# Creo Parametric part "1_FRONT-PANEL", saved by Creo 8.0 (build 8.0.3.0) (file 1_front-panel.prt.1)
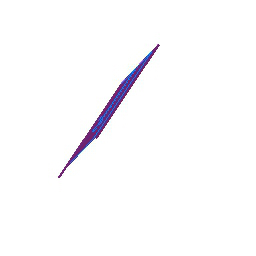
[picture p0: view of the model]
Units: millimeter Newton Second (mmNs); MM, TONNE, SECS

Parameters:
  SMT_DFLT_BEND_REL_LENGTH_TYPE = "Through All"

Other parameters: SMT_THICKNESS, SMT_PART_BEND_ALLOWANCE_FACTOR, SMT_DFLT_BEND_RADIUS, SMT_DFLT_BEND_ANGLE, SMT_DFLT_CRNR_REL_WIDTH, SMT_DFLT_CRNR_REL_DEPTH, SMT_DFLT_BEND_REL_WIDTH, SMT_DFLT_BEND_REL_DEPTH, SMT_DFLT_BEND_REL_LENGTH, SMT_DFLT_BEND_REL_ANGLE, SMT_GAP, SMT_DFLT_EDGE_TREA_WIDTH, SMT_DFLT_MITER_CUT_WIDTH, SMT_DFLT_MITER_CUT_OFFSET

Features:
  1. datum plane "DTM1"
  2. datum plane "DTM2"
  3. datum plane "DTM3"
  4. coordinate system
  5. datum plane "DTM4"
  6. datum plane "DTM5"
  7. round
  8. round
  9. round
  10. cut
  11. cut
  12. cut
  13. curve

Other named items: RIGHT, TOP, FRONT, CS0, CS1

Layers: 0_ALL_AXIS, 0_ALL_CSYS, 0_ALL_CURVES, 0_ALL_PLANES, 0_ALL_POINTS, 0_ALL_SURFS, FRONT-PANEL

Surfaces: 30 plane, 19 cylinder, 10 torus, 2 fillet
